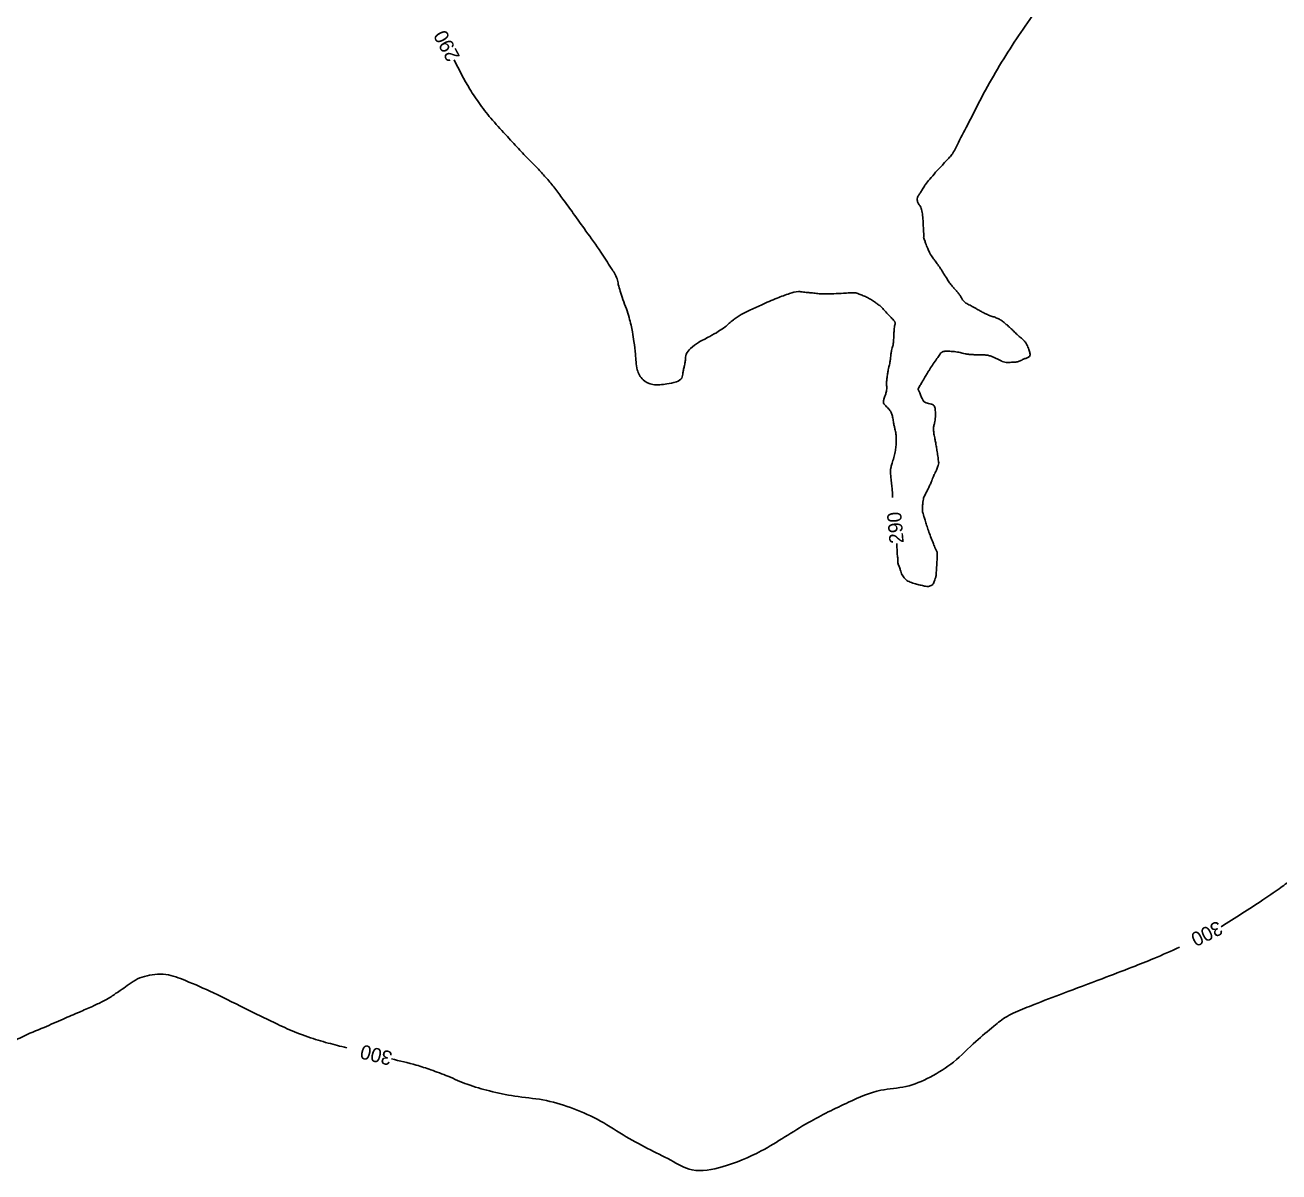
# Model space of a CAD drawing. Extents: x -475575 to -473225, y -1116053 to -1114104.
# Drawn here: x -475113.2 to -474761.3, y -1114766 to -1114444.1 of the extents above; entities that cross this region are included whole.
import ezdxf

# ---------------------------------------------------------------- set-up
doc = ezdxf.new("R2010")
doc.units = 0
doc.layers.add('Vrstevnice_hlavni', color=7, linetype='Continuous')
doc.layers.add('Vrstevnice_popis', color=7, linetype='Continuous')

msp = doc.modelspace()

# ---------------------------------------------------------------- linework, layer by layer
at = {"layer": 'Vrstevnice_hlavni'}
for points in [[(-475049.76, -1114348.75), (-475050.03, -1114349.06), (-475050.19, -1114349.2), (-475050.39, -1114349.32), (-475050.62, -1114349.44), (-475051.19, -1114349.58), (-475052.1, -1114349.76), (-475053.37, -1114349.96), (-475056.71, -1114349.42), (-475062.14, -1114348.12), (-475069.64, -1114346.09), (-475075.28, -1114345.23), (-475079.04, -1114345.54), (-475080.93, -1114347.03), (-475082.39, -1114348.43), (-475083.41, -1114349.74), (-475084.01, -1114350.95), (-475084.63, -1114352.12), (-475085.26, -1114353.27), (-475085.91, -1114354.37), (-475086.65, -1114355.71), (-475087.48, -1114357.27), (-475088.4, -1114359.07), (-475090.61, -1114362.26), (-475094.1, -1114366.84), (-475098.87, -1114372.82), (-475103.89, -1114377.82), (-475109.16, -1114381.82), (-475114.67, -1114384.84), (-475118.65, -1114387.53), (-475121.08, -1114389.89), (-475121.98, -1114391.93), (-475122.62, -1114393.48), (-475123, -1114394.53), (-475123.13, -1114395.1), (-475123.36, -1114395.77), (-475123.68, -1114396.56), (-475124.09, -1114397.45), (-475125.66, -1114400.87), (-475128.41, -1114406.82), (-475132.33, -1114415.29), (-475135.87, -1114422.74), (-475139.05, -1114429.17), (-475141.85, -1114434.59), (-475145.43, -1114439.9), (-475149.77, -1114445.11), (-475154.89, -1114450.23), (-475159.45, -1114455.46), (-475163.47, -1114460.8), (-475166.95, -1114466.26), (-475169.43, -1114470.03), (-475170.91, -1114472.1), (-475171.4, -1114472.49), (-475171.83, -1114472.96), (-475172.18, -1114473.52), (-475172.47, -1114474.16), (-475172.97, -1114474.88), (-475173.69, -1114475.68), (-475174.63, -1114476.54), (-475175.57, -1114477.43), (-475176.5, -1114478.32), (-475177.42, -1114479.22), (-475178.83, -1114480.41), (-475180.73, -1114481.89), (-475183.12, -1114483.65), (-475185.77, -1114486.73), (-475188.68, -1114491.12), (-475191.86, -1114496.83), (-475194.68, -1114500.53), (-475197.14, -1114502.21), (-475199.25, -1114501.88), (-475200.83, -1114501.68), (-475201.89, -1114501.59), (-475202.96, -1114501.67)], [(-474824.9, -1114433.69), (-474834.97, -1114447.99), (-474839.72, -1114455.49), (-474844.2, -1114463.32), (-474848.4, -1114471.5), (-474851.28, -1114477.08), (-474852.85, -1114480.06), (-474853.11, -1114480.43), (-474854, -1114481.45), (-474855.52, -1114483.12), (-474857.66, -1114485.43), (-474859.32, -1114487.33), (-474860.49, -1114488.81), (-474861.16, -1114489.87), (-474861.76, -1114490.83), (-474862.29, -1114491.69), (-474862.73, -1114492.45), (-474862.83, -1114493.25), (-474862.58, -1114494.08), (-474861.98, -1114494.94), (-474861.54, -1114496.24), (-474861.26, -1114497.98), (-474861.15, -1114500.14), (-474861.06, -1114501.7), (-474861.01, -1114502.64), (-474860.98, -1114502.96), (-474860.98, -1114503.23), (-474861, -1114503.44), (-474861.05, -1114503.59), (-474860.87, -1114504.2), (-474860.48, -1114505.27), (-474859.87, -1114506.8), (-474859.39, -1114507.92), (-474859.04, -1114508.62), (-474858.82, -1114508.91), (-474858.41, -1114509.47), (-474857.8, -1114510.3), (-474857, -1114511.41), (-474856.37, -1114512.31), (-474855.93, -1114512.98), (-474855.66, -1114513.44), (-474855.24, -1114514.12), (-474854.66, -1114515.02), (-474853.92, -1114516.15), (-474853.21, -1114517.14), (-474852.52, -1114517.99), (-474851.85, -1114518.7), (-474851.24, -1114519.44), (-474850.69, -1114520.22), (-474850.2, -1114521.03), (-474849.69, -1114521.67), (-474849.16, -1114522.13), (-474848.61, -1114522.43), (-474848.01, -1114522.75), (-474847.37, -1114523.1), (-474846.67, -1114523.48), (-474845.9, -1114523.91), (-474845.04, -1114524.38), (-474844.1, -1114524.9), (-474843.11, -1114525.37), (-474842.07, -1114525.78), (-474840.98, -1114526.13), (-474839.99, -1114526.57), (-474839.09, -1114527.1), (-474838.28, -1114527.73), (-474837.41, -1114528.47), (-474836.48, -1114529.32), (-474835.49, -1114530.29), (-474834.59, -1114531.14), (-474833.78, -1114531.87), (-474833.05, -1114532.5), (-474832.47, -1114533.14), (-474832.04, -1114533.81), (-474831.76, -1114534.5), (-474831.53, -1114535.13), (-474831.34, -1114535.7), (-474831.19, -1114536.22), (-474831.17, -1114536.65), (-474831.26, -1114536.98), (-474831.48, -1114537.22), (-474831.78, -1114537.42), (-474832.15, -1114537.6), (-474832.6, -1114537.73), (-474833.05, -1114537.91), (-474833.5, -1114538.12), (-474833.95, -1114538.37), (-474834.42, -1114538.55), (-474834.92, -1114538.66), (-474835.44, -1114538.69), (-474836.04, -1114538.73), (-474836.71, -1114538.78), (-474837.47, -1114538.82), (-474838.22, -1114538.74), (-474838.95, -1114538.53), (-474839.67, -1114538.18), (-474840.43, -1114537.81), (-474841.25, -1114537.44)], [(-474928.22, -1114539.97), (-474928.27, -1114540.12), (-474928.4, -1114540.71), (-474928.62, -1114541.72), (-474928.93, -1114543.16), (-474930.43, -1114544.19), (-474933.13, -1114544.8), (-474937.03, -1114544.99), (-474939.79, -1114543.67), (-474941.42, -1114540.83), (-474941.91, -1114536.48), (-474942.36, -1114532.95), (-474942.77, -1114530.23), (-474943.15, -1114528.32), (-474943.72, -1114526.17), (-474944.48, -1114523.75), (-474945.43, -1114521.09), (-474946.18, -1114518.79), (-474946.73, -1114516.87), (-474947.09, -1114515.32), (-474948.72, -1114512.31), (-474951.62, -1114507.85), (-474955.81, -1114501.92), (-474959.37, -1114496.95), (-474962.28, -1114492.94), (-474964.57, -1114489.9), (-474966.85, -1114487.11), (-474969.14, -1114484.57), (-474971.42, -1114482.28), (-474974.33, -1114479.23), (-474977.87, -1114475.4), (-474982.03, -1114470.8), (-474985.55, -1114466.36), (-474988.41, -1114462.08), (-474992.84, -1114453.86)], [(-474869.74, -1114576.69), (-474869.76, -1114575.69), (-474869.84, -1114574.75), (-474869.98, -1114573.36), (-474870.19, -1114571.54), (-474870.31, -1114570.17), (-474870.35, -1114569.25), (-474870.3, -1114568.79), (-474870.11, -1114567.94), (-474869.78, -1114566.72), (-474869.3, -1114565.11), (-474868.97, -1114563.53), (-474868.79, -1114561.98), (-474868.75, -1114560.45), (-474868.79, -1114559.19), (-474868.91, -1114558.2), (-474869.1, -1114557.48), (-474869.3, -1114556.56), (-474869.52, -1114555.45), (-474869.75, -1114554.14), (-474870.07, -1114553.08), (-474870.48, -1114552.27), (-474870.98, -1114551.72), (-474871.43, -1114551.23), (-474871.83, -1114550.79), (-474872.18, -1114550.42), (-474872.28, -1114549.76), (-474872.11, -1114548.83), (-474871.68, -1114547.62), (-474871.43, -1114546.62), (-474871.36, -1114545.83), (-474871.46, -1114545.25), (-474871.46, -1114544.41), (-474871.35, -1114543.32), (-474871.15, -1114541.98), (-474870.96, -1114540.89), (-474870.79, -1114540.07), (-474870.63, -1114539.5), (-474870.48, -1114538.71), (-474870.34, -1114537.69), (-474870.21, -1114536.44), (-474870.05, -1114535.43), (-474869.88, -1114534.66), (-474869.69, -1114534.13), (-474869.54, -1114533.24), (-474869.43, -1114532), (-474869.36, -1114530.39), (-474869.28, -1114529.22), (-474869.19, -1114528.49), (-474869.08, -1114528.19), (-474869.02, -1114527.93), (-474869.02, -1114527.71), (-474869.08, -1114527.52), (-474869.17, -1114527.33), (-474869.3, -1114527.14), (-474869.48, -1114526.95), (-474869.97, -1114526.42), (-474870.77, -1114525.54), (-474871.9, -1114524.32), (-474872.67, -1114523.48), (-474873.1, -1114523.03), (-474873.17, -1114522.96), (-474873.57, -1114522.67), (-474874.32, -1114522.15), (-474875.41, -1114521.41), (-474876.53, -1114520.75), (-474877.68, -1114520.18), (-474878.87, -1114519.7), (-474879.76, -1114519.38), (-474880.35, -1114519.22), (-474880.64, -1114519.23), (-474881.72, -1114519.27), (-474883.57, -1114519.36), (-474886.21, -1114519.5), (-474888.47, -1114519.54), (-474890.34, -1114519.49), (-474891.83, -1114519.34), (-474893.3, -1114519.19), (-474894.75, -1114519.04), (-474896.18, -1114518.9), (-474898.65, -1114519.45), (-474902.13, -1114520.71), (-474906.65, -1114522.67), (-474910.02, -1114524.21), (-474912.25, -1114525.34), (-474913.34, -1114526.05), (-474914.45, -1114526.86), (-474915.59, -1114527.79), (-474916.76, -1114528.82), (-474918.59, -1114530.06), (-474921.08, -1114531.51), (-474924.24, -1114533.18), (-474926.43, -1114534.84), (-474927.66, -1114536.5), (-474927.92, -1114538.16), (-474928.11, -1114539.31), (-474928.22, -1114539.97)], [(-474841.25, -1114537.44), (-474842.11, -1114537.05), (-474843.05, -1114536.79), (-474844.09, -1114536.67), (-474845.21, -1114536.67), (-474846.32, -1114536.64), (-474847.41, -1114536.58), (-474848.48, -1114536.49), (-474849.41, -1114536.36), (-474850.18, -1114536.21), (-474850.81, -1114536.02), (-474851.55, -1114535.87), (-474852.39, -1114535.76), (-474853.34, -1114535.69), (-474854.1, -1114535.65), (-474854.68, -1114535.64), (-474855.06, -1114535.66), (-474855.41, -1114535.72), (-474855.71, -1114535.81), (-474855.97, -1114535.95), (-474856.5, -1114536.57), (-474857.29, -1114537.66), (-474858.34, -1114539.23), (-474859.09, -1114540.35), (-474859.53, -1114541.02), (-474859.65, -1114541.23), (-474860.03, -1114541.88), (-474860.66, -1114542.94), (-474861.55, -1114544.44), (-474862.16, -1114545.47), (-474862.51, -1114546.06), (-474862.6, -1114546.19), (-474862.61, -1114546.32), (-474862.57, -1114546.45), (-474862.46, -1114546.58), (-474862.27, -1114546.98), (-474861.99, -1114547.65), (-474861.63, -1114548.59), (-474861.3, -1114549.28), (-474861, -1114549.73), (-474860.72, -1114549.92), (-474860.28, -1114550.11), (-474859.65, -1114550.3), (-474858.86, -1114550.48), (-474858.29, -1114550.77), (-474857.95, -1114551.16), (-474857.84, -1114551.65), (-474857.77, -1114552.3), (-474857.74, -1114553.09), (-474857.74, -1114554.05), (-474857.82, -1114554.96), (-474857.97, -1114555.83), (-474858.19, -1114556.67), (-474858.24, -1114557.69), (-474858.13, -1114558.88), (-474857.86, -1114560.25), (-474857.65, -1114561.36), (-474857.49, -1114562.2), (-474857.4, -1114562.78), (-474857.3, -1114563.45), (-474857.18, -1114564.23), (-474857.06, -1114565.12), (-474856.95, -1114565.86), (-474856.87, -1114566.46), (-474856.8, -1114566.93), (-474856.96, -1114567.68), (-474857.33, -1114568.71), (-474857.93, -1114570.03), (-474858.37, -1114571.02), (-474858.65, -1114571.7), (-474858.76, -1114572.06), (-474859.04, -1114572.71), (-474859.47, -1114573.63), (-474860.07, -1114574.83), (-474860.52, -1114575.73), (-474860.82, -1114576.32), (-474860.98, -1114576.61), (-474861.12, -1114577.17), (-474861.23, -1114578.01), (-474861.33, -1114579.13), (-474861.35, -1114580.03), (-474861.31, -1114580.72), (-474861.19, -1114581.2), (-474860.97, -1114581.99), (-474860.64, -1114583.08), (-474860.2, -1114584.49), (-474859.68, -1114586.01), (-474859.08, -1114587.66), (-474858.4, -1114589.42), (-474857.88, -1114590.7), (-474857.53, -1114591.51), (-474857.34, -1114591.84), (-474857.25, -1114592.75), (-474857.27, -1114594.22), (-474857.4, -1114596.27), (-474857.48, -1114597.68), (-474857.52, -1114598.47)], [(-474857.52, -1114598.47), (-474857.52, -1114598.62), (-474857.65, -1114599.07), (-474857.91, -1114599.8), (-474858.29, -1114600.82), (-474858.95, -1114601.44), (-474859.88, -1114601.67), (-474861.08, -1114601.49), (-474862.35, -1114601.21), (-474863.7, -1114600.82), (-474865.13, -1114600.32), (-474866.25, -1114599.52), (-474867.07, -1114598.43), (-474867.58, -1114597.03), (-474867.93, -1114596.05), (-474868.14, -1114595.49), (-474868.19, -1114595.35), (-474868.26, -1114594.63), (-474868.35, -1114593.34), (-474868.59, -1114589.6)], [(-474777.57, -1114697.2), (-474765.86, -1114689.67), (-474761.25, -1114686.5), (-474757.88, -1114683.93), (-474755.76, -1114681.97), (-474752.41, -1114678.95), (-474747.82, -1114674.87), (-474742, -1114669.74), (-474736.32, -1114665.33), (-474730.78, -1114661.64), (-474725.39, -1114658.67), (-474717.35, -1114656.2), (-474706.67, -1114654.22), (-474693.33, -1114652.74), (-474680.34, -1114650.84), (-474667.68, -1114648.52), (-474655.36, -1114645.78), (-474646.81, -1114643.91), (-474642.03, -1114642.92), (-474641.01, -1114642.79), (-474640.1, -1114642.65), (-474639.29, -1114642.49), (-474638.58, -1114642.31), (-474633.9, -1114641.97), (-474625.25, -1114641.47), (-474612.62, -1114640.8), (-474600, -1114640.58), (-474587.38, -1114640.8), (-474574.75, -1114641.47), (-474566.1, -1114641.88), (-474561.42, -1114642.04), (-474560.71, -1114641.95), (-474559.97, -1114641.94), (-474559.21, -1114642.02), (-474558.42, -1114642.2), (-474556.67, -1114642.43), (-474553.94, -1114642.74), (-474546.56, -1114643.47)], [(-474789.19, -1114702.93), (-474796.4, -1114706.09), (-474802.46, -1114708.51), (-474810.97, -1114711.78), (-474821.93, -1114715.89), (-474830.03, -1114719.02), (-474835.27, -1114721.18), (-474837.63, -1114722.37), (-474841.32, -1114725.09), (-474846.34, -1114729.36), (-474852.68, -1114735.17), (-474859.24, -1114739.4), (-474866.01, -1114742.03), (-474873.01, -1114743.08), (-474882.11, -1114746.45), (-474893.33, -1114752.13), (-474906.67, -1114760.13), (-474917.56, -1114764.56), (-474926.02, -1114765.42), (-474932.04, -1114762.71), (-474938.5, -1114759.44), (-474945.38, -1114755.61), (-474952.69, -1114751.23), (-474960.19, -1114747.95), (-474967.89, -1114745.79), (-474975.79, -1114744.74), (-474982.86, -1114743.28), (-474989.12, -1114741.42), (-474994.56, -1114739.15), (-474999.34, -1114737.35), (-475003.47, -1114736.02), (-475010.41, -1114734.28)], [(-475129.44, -1114744.73), (-475129.31, -1114744.56), (-475129.22, -1114744.44), (-475129.16, -1114744.37), (-475129.14, -1114744.35), (-475129.11, -1114744.22), (-475129.07, -1114743.99), (-475129.02, -1114743.67), (-475128.97, -1114743.58), (-475128.91, -1114743.74), (-475128.84, -1114744.14), (-475128.6, -1114744.44), (-475128.21, -1114744.64), (-475127.64, -1114744.74), (-475127.2, -1114744.7), (-475126.88, -1114744.51), (-475126.68, -1114744.19), (-475126.4, -1114743.63), (-475126.04, -1114742.85), (-475125.61, -1114741.85), (-475125.29, -1114741.03), (-475125.08, -1114740.39), (-475124.98, -1114739.95), (-475124.82, -1114739.15), (-475124.6, -1114737.99), (-475124.33, -1114736.48), (-475124.02, -1114735.31), (-475123.68, -1114734.5), (-475123.31, -1114734.03), (-475122.9, -1114733.63), (-475122.45, -1114733.3), (-475121.97, -1114733.03), (-475121.53, -1114732.64), (-475121.14, -1114732.13), (-475120.8, -1114731.51), (-475118.49, -1114730.18), (-475114.2, -1114728.16), (-475107.93, -1114725.45), (-475102.54, -1114723.1), (-475098.01, -1114721.14), (-475094.36, -1114719.54), (-475091.49, -1114718.18), (-475089.42, -1114717.06), (-475088.14, -1114716.16), (-475086.53, -1114715.05), (-475084.58, -1114713.71), (-475082.29, -1114712.16), (-475079.72, -1114711.12), (-475076.87, -1114710.6), (-475073.73, -1114710.6), (-475068.24, -1114712.3), (-475060.4, -1114715.7), (-475050.2, -1114720.8), (-475042.38, -1114724.56), (-475036.94, -1114726.99), (-475033.88, -1114728.08), (-475030.97, -1114729.03), (-475028.21, -1114729.83), (-475022.98, -1114731.14)]]:
    msp.add_spline(points, degree=3, dxfattribs=at)

# ---------------------------------------------------------------- texts
at = {"layer": 'Vrstevnice_popis'}
for s, rotation, p in [(' 290 ', 118.3008, (-474990.35, -1114454.25)), (' 290 ', 95.1105, (-474866.46, -1114590.94)), (' 300 ', 206.276, (-474777.09, -1114694.73)), (' 300 ', 165.9638, (-475008.45, -1114732.71))]:
    msp.add_text(s, height=4, rotation=rotation, dxfattribs=at).set_placement(p)

doc.saveas('drawing.dxf')
